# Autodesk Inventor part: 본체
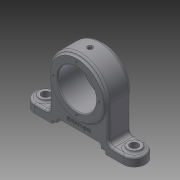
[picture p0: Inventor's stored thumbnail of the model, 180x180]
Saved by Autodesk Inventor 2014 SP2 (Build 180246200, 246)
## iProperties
Created: 2019-05
Part Number: 본체
Material: Generic
Document SubType Name: Modeling
Designer: gs
Density: 1 g/cm^3
Appearance: Default
Author: gs
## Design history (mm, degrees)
sketch "스케치1"
  geometry: L1 (-75, 0)-(75, 0); L2 (75, 0)-(75, 12); L3 (-75, 12)-(-75, 0); L4 (-40, 60)-(-40, 12); L5 (40, 60)-(40, 12); L6 (75, 12)-(40, 12); L7 (-40, 12)-(-75, 12); A1 r 40 centre (0, 60) between (40, 60) and (-40, 60); 2 further points
  constraints: 14 end point, 3 parallel, 3 perpendicular, 2 point on circle, 2 tangent, 1 centre point, 1 coincident, 1 horizontal, 1 midpoint, 1 vertical alignment
  dimensions: "d0" = 150 distance between parallel lines of L2 L3; "d2" = 40 radius of A1; "d3" = 60 distance from line of L1 A1.centre; "d4" = 12 distance between parallel lines of L6 L1; "d5" = 0 distance between parallel lines of L6 L7; "d37" = 100 dimension on A1 L1 (derived)
extrude "돌출1" new body sketch "스케치1" stored distance "d6" = 30; taper "d7" = 0 deg; taper "d17" = 0 deg
sketch "스케치3"
  geometry: C1 r 36 at (0, 60); A1 r 40 centre (0, 60) between (40, 60) and (-40, 60) reference; 1 further point
  constraints: 1 centre point, 1 coincident
  dimensions: "d11" = 72 diameter of C1
extrude "돌출3" join sketch "스케치3" distance "d12" = 3; taper "d13" = 0 deg
sketch "스케치4"
  geometry: L1 (-75, 0)-(75, 0) reference; L2 (-30, 0)-(30, 0); L3 (30, 0)-(30, 10); L4 (30, 10)-(-30, 10); L5 (-30, 10)-(-30, 0); 3 further points
  constraints: 8 end point, 2 midpoint, 2 parallel, 1 coincident, 1 collinear, 1 horizontal, 1 perpendicular
  dimensions: "d14" = 60 distance between parallel lines of L3 L5; "d15" = 10 distance between parallel lines of L1 L4
extrude "돌출4" cut sketch "스케치4" stored distance "d16" = 3; taper "d17" = 0 deg
sketch "스케치5"
  geometry: L1 (-75, 0)-(-30, 0) reference; L2 (-36, 0)-(36, 0); L3 (36, 0)-(36, 4); L4 (36, 4)-(-36, 4); L5 (-36, 4)-(-36, 0); 2 further points
  constraints: 8 end point, 2 parallel, 1 coincident, 1 collinear, 1 horizontal, 1 midpoint, 1 perpendicular
  dimensions: "d18" = 72 distance between parallel lines of L3 L5; "d19" = 4 distance between parallel lines of L2 L4
extrude "돌출5" cut sketch "스케치5" stored distance "d21" = 3; taper "d22" = 0 deg
sketch "스케치6"
  geometry: L1 (0, 0)-(35, 0) reference; L2 (0, -30)-(0, 0) reference; C1 r 9 at (15, -15); 1 further point
  constraints: 1 centre point
  dimensions: "d23" = 18 diameter of C1; "d24" = 15 distance from line of L2 C1.centre; "d25" = 15 distance from line of L1 C1.centre
extrude "돌출6" join sketch "스케치6" distance "d26" = 3; taper "d27" = 0 deg
hole "구멍1" diameter "d30" = 11; stored, may be unused: countersink angle "d34" = 90 deg, drill point angle "d36" = 118 deg; dims "d28" = 10, "d29" = 10, "d31" = 6, "d32" = 4, "d33" = 2, "d35" = 8
node "작업 평면1"
sketch "스케치7"
  geometry: C1 r 3.5 at (0, 0); 1 further point
  constraints: 1 centre point, 1 coincident
  dimensions: "d39" = 7 diameter of C1
extrude "돌출7" cut sketch "스케치7" distance "d40" = 1; taper "d41" = 0 deg
hole "구멍2" diameter "d44" = 4.917; stored, may be unused: countersink angle "d48" = 90 deg, drill point angle "d50" = 118 deg; dims "d42" = 10, "d43" = 10, "d45" = 8, "d46" = 4, "d47" = 2, "d49" = 10
hole "구멍3" diameter "d53" = 52; stored, may be unused: countersink angle "d57" = 90 deg, drill point angle "d59" = 118 deg; dims "d51" = 10, "d52" = 10, "d54" = 52, "d55" = 4, "d56" = 2, "d58" = 52
sketch "스케치8" dims "d60" = 62
  geometry: C1 r 26 at (0, 0) reference; C2 r 36 at (0, 0) reference; 3 further points
  constraints: 2 vertical alignment, 1 coincident, 2 other
hole "구멍4" sketch "스케치8" at (0, 31) diameter "d62" = 3.242; stored, may be unused: countersink angle "d66" = 90 deg, drill point angle "d68" = 118 deg; dims "d63" = 6, "d64" = 4, "d65" = 2, "d67" = 8
sketch "스케치10"
  geometry: C1 r 26 at (0, 0) reference; C2 r 36 at (0, 0) reference; C3 r 26 at (0, 0); 2 further points
  constraints: 1 centre point, 1 coincident, 1 vertical alignment
  dimensions: "d72" = 52 diameter of C3; "d73" = 26 distance of C1.centre point (0, 26)
hole "구멍5" sketch "스케치10" at (0, 26) diameter "d74" = 3; stored, may be unused: countersink angle "d78" = 90 deg, drill point angle "d80" = 118 deg; dims "d75" = 6, "d76" = 4, "d77" = 2, "d79" = 8
hole "구멍6" diameter "d83" = 2; stored, may be unused: countersink angle "d87" = 90 deg, drill point angle "d89" = 0 deg; dims "d84" = 6, "d85" = 4, "d86" = 2, "d88" = 20, "d90" = 10, "d91" = 10
node "작업 평면2"
sketch "스케치11"
  geometry: C1 r 1 at (0, 0); 1 further point
  constraints: 1 centre point, 1 coincident
  dimensions: "d93" = 2 diameter of C1
extrude "돌출8" cut sketch "스케치11" stored distance "d94" = 20; taper "d95" = 0 deg
sketch "스케치12"
  geometry: L1 (-30, 10)-(30, 10) reference; L2 (-20, 20)-(20, 20); L3 (20, 20)-(20, 14); L4 (20, 14)-(-20, 14); L5 (-20, 14)-(-20, 20); L6 (-20, 17)-(20, 17); L7 (0, 20)-(0, 14); 1 further point
  constraints: 4 end point, 4 midpoint, 1 vertical alignment, 2 other
  dimensions: "d96" = 40 distance of L6.start L6.end; "d97" = 6 distance of L7.start L7.end; "d98" = 7 distance between parallel lines of L1 L6
feature "엠보싱1" sketch "스케치12" dims "d99" = 0.5, "d100" = 0
chamfer "모따기1" distance "d102" = 1; stored, may be unused: second distance "d103" = 2, angle "d104" = 45 deg
fillet "모깎기3" dims "d106" = 15
fillet "모깎기4" dims "d107" = 15
fillet "모깎기5" dims "d108" = 15
fillet "모깎기6" dims "d109" = 6
fillet "모깎기7" dims "d110" = 3
fillet "모깎기8" dims "d111" = 3
fillet "모깎기9" dims "d112" = 3
fillet "모깎기10" dims "d113" = 3
fillet "모깎기11" dims "d114" = 3
node "솔리드1"
mirror "대칭1"
mirror "대칭2"
mirror "대칭3"
pattern_circular "원형 패턴1" dims angle "d70" = 360 deg
mirror "대칭4"
other parameters: "d1" = 12, "d92" = 86
